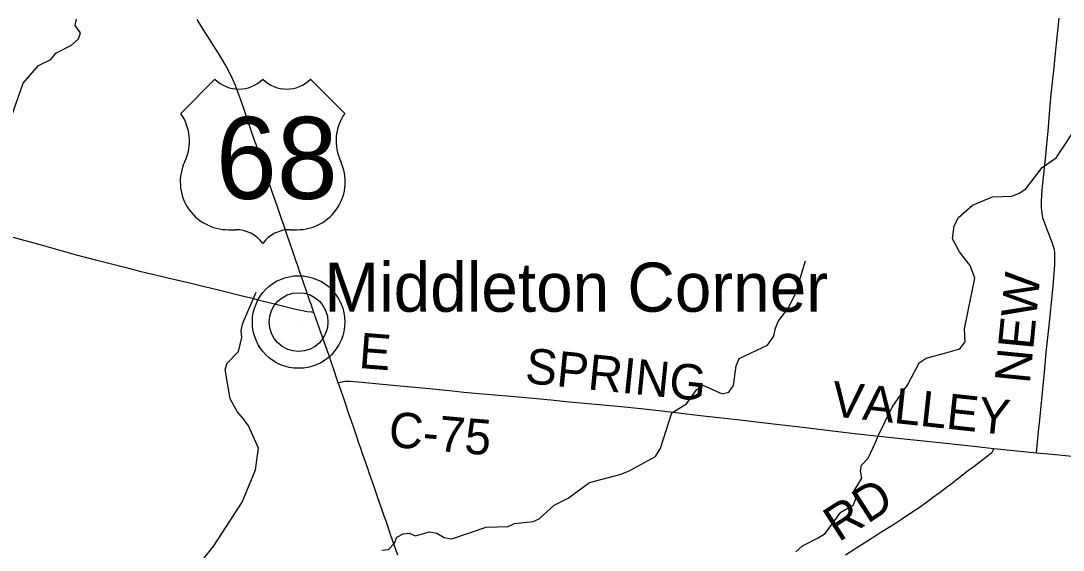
# Model space of a CAD drawing. Extents: x 1410790 to 1770854, y 448063 to 770588.
# Drawn here: x 1582368 to 1591219, y 576622 to 581114 of the extents above; entities that cross this region are included whole.
import ezdxf

# ---------------------------------------------------------------- set-up
doc = ezdxf.new("R2010")
doc.units = 0
for name, color, linetype in [('GM_X_County_Road', 7, 'Continuous'), ('GM_X_County_Road_Text', 7, 'Continuous'), ('GM_X_Minor_River', 7, 'Continuous'), ('GM_X_Township_Road', 7, 'Continuous'), ('GM_X_Township_Road_Text', 7, 'Continuous'), ('GM_X_Unincorporated', 7, 'Continuous'), ('GM_X_Unincorporated_Location', 7, 'Continuous'), ('GM_X_Unincorporated_Text', 7, 'Continuous'), ('GM_X_US_Location', 7, 'Continuous'), ('GM_X_US_Route', 7, 'Continuous'), ('GM_X_US_Shield', 7, 'Continuous')]:
    doc.layers.add(name, color=color, linetype=linetype)

msp = doc.modelspace()

# ---------------------------------------------------------------- linework, layer by layer
at = {"layer": 'GM_X_County_Road'}
for points in [[(1582196.1, 579307.8), (1582448.3, 579238), (1582559.4, 579207), (1582700.6, 579168.2), (1582837.9, 579129.7), (1583003.1, 579086.6), (1583251.1, 579023.7), (1583378.4, 578991.4), (1583496.3, 578962.6), (1583643.1, 578927.5), (1583825.3, 578885.6), (1583927.2, 578860.7), (1584057.7, 578828.1), (1584236, 578784.1), (1584322, 578762.8), (1584382.5, 578747.9), (1584509.9, 578716.7), (1584704.2, 578668.6), (1584759, 578656.9), (1584799, 578648.9), (1584835.6, 578643.5), (1584856.8, 578640.3)], [(1585063.7, 578043.1), (1585081.6, 578047.7), (1585097.9, 578051.9), (1585118.5, 578055.6), (1585133, 578057), (1585150.8, 578056.6), (1585168.1, 578055.6), (1585262.8, 578048.4), (1585439.3, 578032.1), (1585589.4, 578017.2), (1585808.1, 577996.8), (1586033.3, 577973.9), (1586131.2, 577964.4), (1586389.2, 577941.5), (1586529.6, 577929.4), (1586777.6, 577905.3), (1586868.9, 577896.7), (1586996.3, 577884.8), (1587185.7, 577866.7), (1587466.6, 577840.3), (1587633, 577823.5), (1587838.3, 577800.8), (1588115.3, 577769), (1588525.9, 577721.5), (1588659.4, 577705.4), (1588982, 577667.5), (1589447.4, 577613.7), (1589893.7, 577564.4), (1590007.9, 577552.3), (1590357.1, 577516.4), (1590534.6, 577496.5), (1590630.2, 577485.8)], [(1590991.8, 577449), (1591059.7, 577442.9), (1591095.6, 577439.6), (1591498.7, 577401.2), (1591636.8, 577387.9), (1591650.1, 577386.3), (1591665.4, 577385.6), (1591681.4, 577385.2), (1591701.3, 577387.1), (1591715.8, 577389.9), (1591735, 577394.9), (1591747.5, 577398.5), (1591761.2, 577403.9), (1591774.5, 577410.2), (1591789.8, 577419.5), (1591822.4, 577440.5), (1591892.2, 577494.6), (1591935.8, 577529.7), (1591968.1, 577552.8), (1591992.2, 577567), (1592016, 577580.1), (1592033, 577588.6), (1592054.6, 577596.4)], [(1590630.2, 577485.8), (1590991.8, 577449)]]:
    msp.add_lwpolyline(points, dxfattribs=at)
at = {"layer": 'GM_X_Minor_River'}
for points in [[(1590845, 579650.7), (1590901.6, 579690), (1591039.9, 579868.7), (1591159.1, 579953.3), (1591354.8, 580247.4), (1591597.7, 580454.8), (1591650.2, 580498.2), (1591769.6, 580598.9), (1591847.1, 580712.1), (1591860.5, 580830.2), (1591823.7, 581107.3), (1591863.3, 581233.1)], [(1582266, 580237.1), (1582388.3, 580586.3), (1582518.3, 580737), (1582623, 580785.7), (1582665.7, 580839.3), (1582798.7, 580907.8), (1582857.4, 580961.1), (1582874.1, 581013), (1582830.8, 581075.7), (1582841.4, 581129.7)], [(1588948.2, 576607.9), (1589004.9, 576659.3), (1589139.9, 576727.7), (1589198.4, 576763), (1589332.7, 576943.8), (1589439.6, 577006.5), (1589458.3, 577060.4), (1589434.9, 577112.8), (1589510.4, 577234.2), (1589497.1, 577292.5), (1589505.7, 577344.5), (1589564.5, 577403.9), (1589622.1, 577529.5), (1589648.9, 577593.3), (1589767.9, 577836.3), (1589900.4, 578027.1), (1589996.7, 578212.3), (1590055.3, 578251.6), (1590224, 578297.5), (1590342.6, 578332.1), (1590387.4, 578389.6), (1590380.7, 578500), (1590469.9, 578929.8), (1590429.1, 579038.6), (1590387.7, 579093.3), (1590338.4, 579154.1), (1590279.6, 579263.1), (1590293, 579375.2), (1590329.8, 579444.9), (1590449.3, 579549.6), (1590620.3, 579621.5), (1590784.6, 579625.4), (1590845, 579650.7)], [(1585433.4, 576621.5), (1585491.6, 576628.8), (1585540.3, 576680.3), (1585560.9, 576732.2), (1585615.3, 576761.5), (1585665.5, 576766.9), (1585719.3, 576744.1), (1585837.8, 576776.7), (1585901.8, 576767.8), (1585963.4, 576728.9), (1586029.4, 576718.1), (1586321, 576818.5), (1586507.3, 576822.1), (1586559.7, 576849.5), (1586720.1, 576865.5), (1586770.5, 576888.9), (1586898, 577003.5), (1587014.9, 577062.2), (1587196.7, 577196.1), (1587465.9, 577266.8), (1587538.4, 577297.9), (1587758.1, 577417.4), (1587799, 577489), (1587896.7, 577788.5), (1588019.8, 577865.1), (1588105.3, 577984.3), (1588159.9, 578021.7), (1588325.2, 577949.3), (1588379.5, 577962.7), (1588420.2, 578018.3), (1588442.2, 578186.4), (1588467, 578250.2), (1588708.7, 578363.4), (1588763.7, 578438.8), (1588776.5, 578506.8), (1588799.2, 578562.7), (1588890.8, 578685.8), (1588950.3, 578807.3), (1589031.7, 579078.9)], [(1583867.6, 576483.4), (1584005.9, 576658.1), (1584248.6, 577029.9), (1584360, 577305.2), (1584386.2, 577487.3), (1584302.4, 577676.8), (1584257, 577739.5), (1584205.7, 577798.4), (1584146.9, 577907.4), (1584103.8, 578154.5), (1584120.4, 578210.5), (1584215.7, 578307.4), (1584245.2, 578427.4), (1584237.9, 578487.6), (1584254.7, 578549.5), (1584365.9, 578810.7)]]:
    msp.add_lwpolyline(points, dxfattribs=at)
at = {"layer": 'GM_X_Township_Road'}
for points in [[(1590991.8, 577449), (1591011.4, 577630.1), (1591020.7, 577728), (1591038.3, 577904.4), (1591060, 578133), (1591075.8, 578299.6), (1591101.1, 578527.8), (1591130.4, 578834.8), (1591140.1, 578932.8), (1591148.2, 579044), (1591150.1, 579103), (1591148.9, 579135.8), (1591147.4, 579151.3), (1591144.8, 579167.1), (1591142.2, 579180.9), (1591136.9, 579200.2), (1591123.7, 579240.7), (1591085.5, 579335), (1591059.7, 579402.2), (1591052.5, 579425.1), (1591047.2, 579444.1), (1591043, 579464.1), (1591040.4, 579481), (1591037.2, 579507.9), (1591035.7, 579527.5), (1591035.3, 579551.7), (1591036.7, 579586.5), (1591042.3, 579674.8), (1591045.2, 579707.3), (1591073.4, 579971.3), (1591084.9, 580095.3), (1591091.8, 580176.9), (1591103.6, 580324), (1591110.2, 580399.1), (1591118.7, 580490.6), (1591126.3, 580568.9), (1591141.8, 580718.9), (1591148.7, 580780.8), (1591163.4, 580921), (1591184.6, 581136.3)], [(1590585.5, 577429.7), (1590603.5, 577443.6), (1590613, 577451.7), (1590618.5, 577458), (1590621.3, 577462.3), (1590625.4, 577470.2), (1590628.3, 577478.1), (1590630.2, 577485.8)], [(1589370.3, 576583.4), (1589442.8, 576628.4), (1589467.2, 576644.6), (1589489.5, 576658.5), (1589559.3, 576701.7), (1589644.8, 576756.8), (1589672.4, 576774.4), (1589700.1, 576792), (1589785.8, 576846.6), (1589846.6, 576885.4), (1589917.7, 576932.5), (1589966.9, 576965), (1589980.4, 576974.2), (1590039.2, 577016), (1590092, 577054.8), (1590110.6, 577068.1), (1590174, 577114.7), (1590215.8, 577146.3), (1590268.2, 577185.8), (1590377.2, 577270), (1590415.9, 577300.3), (1590470.9, 577341.7), (1590502.3, 577365.3), (1590585.5, 577429.7)]]:
    msp.add_lwpolyline(points, dxfattribs=at)
at = {"layer": 'GM_X_Unincorporated'}
for radius in [392.8, 249]:
    msp.add_circle((1584727.3, 578558.4), radius, dxfattribs=at)
at = {"layer": 'GM_X_Unincorporated_Location'}
msp.add_line((1584727.3, 578558.4), (1584727.3, 578558.4), dxfattribs=at)
at = {"layer": 'GM_X_US_Route'}
for points in [[(1584994, 578247.5), (1584947.5, 578383), (1584914.2, 578479), (1584905.7, 578503.8), (1584876.8, 578584), (1584856.8, 578640.3), (1584845, 578673.6), (1584835.3, 578701.5), (1584819.9, 578744.7), (1584808, 578778.8), (1584787.7, 578837.6), (1584773.6, 578877.9), (1584756.7, 578927.5), (1584751.5, 578943), (1584732.5, 578998.9), (1584722.9, 579026.7), (1584716.6, 579045.2), (1584710.2, 579063.7), (1584689.5, 579122.5), (1584674.5, 579165.8), (1584648.6, 579240.1), (1584632.7, 579286.6), (1584626.6, 579305.3), (1584612.8, 579345.5), (1584601.2, 579379.7), (1584584, 579429.3), (1584579.7, 579441.7), (1584544.5, 579544), (1584523, 579606), (1584506.2, 579655.6), (1584494.4, 579689.7), (1584480.6, 579730), (1584469.1, 579764.2), (1584456.2, 579801.4), (1584445.5, 579832.4), (1584433.9, 579866.6), (1584405.7, 579947.1), (1584392.8, 579984.3), (1584386.4, 580002.9), (1584365.4, 580065), (1584350.4, 580108.4), (1584338.8, 580142.5), (1584295.4, 580269.8), (1584288, 580291.5), (1584263.7, 580362.9), (1584230.8, 580459.2), (1584206.1, 580527.1), (1584197.9, 580548.6), (1584192.9, 580560.7), (1584180, 580590.9), (1584156.8, 580641.7), (1584143.9, 580668.3), (1584131.9, 580691.8), (1584103.9, 580743.9), (1584075.6, 580792.1), (1584044.6, 580842.5), (1584025.2, 580872.9), (1583984.6, 580936.5), (1583961.7, 580972.5), (1583933.7, 581016.8), (1583865.8, 581125.2)], [(1585569.5, 576579.3), (1585552.5, 576628.9), (1585530.9, 576690.9), (1585502.8, 576771.4), (1585483.6, 576827.2), (1585470, 576867.6), (1585455, 576911), (1585439.8, 576954.4), (1585393.8, 577084.2), (1585364.6, 577167.8), (1585327.1, 577279.8), (1585320.7, 577298.3), (1585298.1, 577363.1), (1585280.4, 577412.4), (1585273.7, 577430.8), (1585252.8, 577492.9), (1585237, 577539.4), (1585230.6, 577558), (1585198.2, 577650.8), (1585172.7, 577725.2), (1585160, 577762.4), (1585107.1, 577917.7), (1585070.5, 578023.1), (1585063.7, 578043.1), (1585057.8, 578060.3), (1585049.3, 578085.1), (1585031.4, 578137.9), (1585006.1, 578212.4), (1584997.6, 578237.2), (1584994, 578247.5)]]:
    msp.add_lwpolyline(points, dxfattribs=at)
at = {"layer": 'GM_X_US_Shield'}
for p, q in [((1584016.5, 580618.3), (1583726.5, 580328.3)), ((1585118.6, 580328.3), (1584828.6, 580618.3)), ((1584132.5, 579342.2), (1584190.5, 579342.2)), ((1584654.6, 579342.2), (1584712.6, 579342.2))]:
    msp.add_line(p, q, dxfattribs=at)
for centre, radius, start, end in [((1584219.5, 580825.5), 290, 225.573, 314.427), ((1584625.6, 580825.5), 290, 225.573, 314.427), ((1583393.8, 580095.4), 406.1, 334.54712, 35.00093), ((1585451.3, 580095.4), 406.1, 144.99907, 205.45288), ((1584128, 579748.2), 406.1, 154.83192, 270.63826), ((1584717.1, 579748.2), 406.1, 269.36174, 25.16808), ((1584190.5, 579052.1), 290, 36.8699, 90), ((1584654.6, 579052.1), 290, 90, 143.1301)]:
    msp.add_arc(centre, radius, start, end, dxfattribs=at)

# ---------------------------------------------------------------- texts
at = {"layer": 'GM_X_County_Road_Text'}
for s, rotation, p in [('E', 355.52698, (1585232.4, 578169.3)), ('SPRING', 354.21211, (1586643, 578041.9)), ('VALLEY', 353.8459, (1589242.2, 577760)), ('C-75', 355.03455, (1585483.7, 577501.2))]:
    msp.add_text(s, height=300, rotation=rotation, dxfattribs=at).set_placement(p)
at = {"layer": 'GM_X_Township_Road_Text'}
for s, rotation, p in [('NEW', 84.40836, (1590935.6, 578029.1)), ('RD', 32.73624, (1589313, 576686))]:
    msp.add_text(s, height=300, rotation=rotation, dxfattribs=at).set_placement(p)
at = {"layer": 'GM_X_Unincorporated_Text'}
msp.add_text('Middleton Corner', height=417, rotation=0.00001, dxfattribs=at).set_placement((1584946.2, 578645.8))
at = {"layer": 'GM_X_US_Location'}
for s in ['/', '0']:
    msp.add_text(s, height=1, dxfattribs=at).set_placement((1584422.2, 579945.8))
msp.add_text('68', height=1, rotation=0.00001, dxfattribs=at).set_placement((1584215.8, 579738.8))
at = {"layer": 'GM_X_US_Shield'}
msp.add_text('68', height=696.1, dxfattribs=at).set_placement((1584024.1, 579603.2))

doc.saveas('drawing.dxf')
